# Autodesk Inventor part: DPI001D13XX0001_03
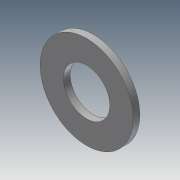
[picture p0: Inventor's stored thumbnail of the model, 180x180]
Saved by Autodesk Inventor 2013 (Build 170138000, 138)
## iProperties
Created: 2014-02
Part Number: DPI001D13XX0001_03
Material: ASTM-A 36
Description: CHAPA - Ø130 x 3/8"
Document SubType Name: Modeling
Designer: luiz.parente
Density: 1 g/cm^3
Author: luiz.parente
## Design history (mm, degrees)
sketch "Sketch1"
  geometry: C1 r 32.5 at (0, 0); C2 r 65 at (0, 0); 1 further point
  constraints: 2 centre point, 2 coincident
  dimensions: "d0" = 65 diameter of C1; "d1" = 130 diameter of C2
extrude "Extrusion1" new body sketch "Sketch1" distance "d2" = 9.525; taper "d3" = 0 deg
body "Solid1"
